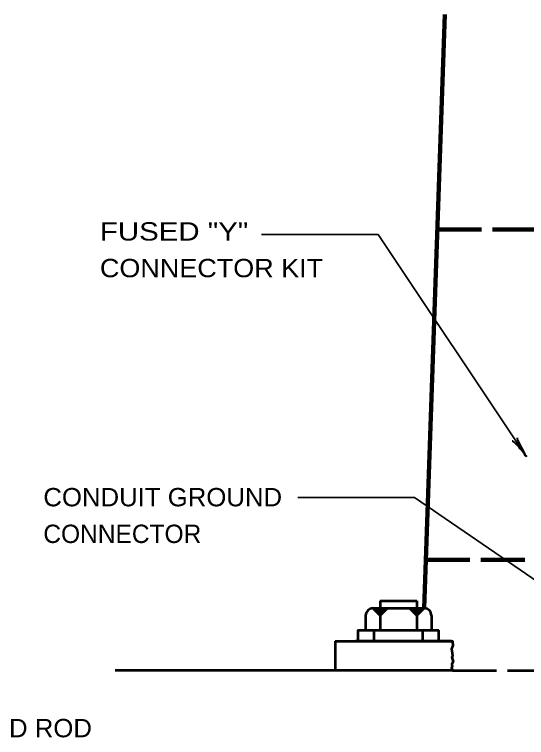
# Model space of a CAD drawing. Extents: x -217 to 639, y -295 to 249.
# Drawn here: x 38.9 to 122.7, y -196.8 to -78.5 of the extents above; entities that cross this region are included whole.
import ezdxf

# ---------------------------------------------------------------- set-up
doc = ezdxf.new("R2010")
doc.units = 0
doc.header["$LTSCALE"] = 1.2
doc.linetypes.add('LONG_DASHED', pattern=[7.5, 6, -1.5])
doc.layers.add('1', color=7, linetype='Continuous', lineweight=53)

msp = doc.modelspace()

# ---------------------------------------------------------------- linework, layer by layer
at = {"layer": '1', "lineweight": 90}
msp.add_line((106, -175.604), (109.392, -78.463), dxfattribs=at)
at = {"layer": '1', "lineweight": 35}
for p, q in [((98.44, -114.451), (79.348, -114.451)), ((98.44, -114.451), (122.733, -150.845)), ((104.401, -157.5), (85.31, -157.5)), ((104.401, -157.5), (141.068, -182.591))]:
    msp.add_line(p, q, dxfattribs=at)
at = {"layer": '1', "linetype": 'LONG_DASHED', "lineweight": 90}
for p, q in [((108.163, -113.668), (159.407, -113.668)), ((106.277, -167.668), (161.293, -167.668))]:
    msp.add_line(p, q, dxfattribs=at)
at = {"layer": '1'}
for p, q in [((98.8, -174.404), (98.8, -179.204)), ((98.8, -174.404), (104.8, -174.404)), ((104.8, -174.404), (104.8, -179.204)), ((97.6, -175.604), (106, -175.604)), ((98.8, -176.804), (97.6, -175.604)), ((97.699, -175.703), (97.798, -175.604)), ((97.715, -175.718), (97.814, -175.619)), ((97.736, -175.739), (97.835, -175.64)), ((97.739, -175.743), (97.839, -175.644)), ((97.745, -175.749), (97.844, -175.65)), ((97.747, -175.75), (97.846, -175.651)), ((97.751, -175.754), (97.85, -175.655)), ((97.758, -175.761), (97.915, -175.604)), ((97.761, -175.765), (97.923, -175.604)), ((97.771, -175.774), (97.941, -175.604)), ((97.775, -175.778), (97.949, -175.604)), ((97.786, -175.79), (97.886, -175.691)), ((97.79, -175.793), (97.979, -175.604)), ((97.797, -175.801), (97.994, -175.604)), ((97.8, -175.803), (97.899, -175.704)), ((97.809, -175.812), (98.017, -175.604)), ((97.813, -175.816), (97.912, -175.717)), ((97.816, -175.82), (97.916, -175.721)), ((97.818, -175.821), (98.036, -175.604)), ((97.831, -175.835), (98.062, -175.604)), ((97.835, -175.839), (97.934, -175.74)), ((97.841, -175.844), (97.94, -175.745)), ((97.844, -175.848), (98.088, -175.604)), ((97.85, -175.853), (98.099, -175.604)), ((97.85, -175.854), (97.949, -175.755)), ((97.854, -175.858), (97.953, -175.759)), ((97.859, -175.863), (98.118, -175.604)), ((97.862, -175.865), (97.961, -175.766)), ((97.865, -175.868), (98.129, -175.604)), ((97.865, -175.868), (98.13, -175.604)), ((97.872, -175.876), (98.145, -175.604)), ((97.878, -175.882), (98.156, -175.604)), ((97.889, -175.893), (98.178, -175.604)), ((97.899, -175.903), (97.998, -175.804)), ((97.903, -175.906), (98.205, -175.604)), ((97.912, -175.916), (98.011, -175.817)), ((97.914, -175.917), (98.227, -175.604)), ((97.918, -175.921), (98.235, -175.604)), ((97.92, -175.924), (98.019, -175.825)), ((97.924, -175.927), (98.023, -175.828)), ((97.927, -175.931), (98.026, -175.832)), ((97.933, -175.937), (98.032, -175.838)), ((97.934, -175.938), (98.269, -175.604)), ((97.944, -175.948), (98.043, -175.849)), ((97.948, -175.951), (98.295, -175.604)), ((97.959, -175.962), (98.318, -175.604)), ((97.959, -175.963), (98.058, -175.864)), ((97.968, -175.972), (98.336, -175.604)), ((97.97, -175.974), (98.34, -175.604)), ((97.983, -175.987), (98.367, -175.604)), ((97.986, -175.989), (98.085, -175.89)), ((97.993, -175.996), (98.385, -175.604)), ((98.002, -176.006), (98.404, -175.604)), ((98.01, -176.013), (98.419, -175.604)), ((98.015, -176.019), (98.431, -175.604)), ((98.021, -176.025), (98.12, -175.926)), ((98.029, -176.032), (98.457, -175.604)), ((98.033, -176.036), (98.132, -175.937)), ((98.034, -176.038), (98.468, -175.604)), ((98.04, -176.043), (98.479, -175.604)), ((98.057, -176.06), (98.513, -175.604)), ((98.06, -176.064), (98.52, -175.604)), ((98.061, -176.065), (98.16, -175.966)), ((98.064, -176.068), (98.528, -175.604)), ((98.072, -176.076), (98.171, -175.977)), ((98.074, -176.077), (98.547, -175.604)), ((98.087, -176.09), (98.573, -175.604)), ((98.087, -176.091), (98.186, -175.992)), ((98.093, -176.096), (98.585, -175.604)), ((98.097, -176.1), (98.196, -176.001)), ((98.1, -176.103), (98.6, -175.604)), ((98.106, -176.109), (98.611, -175.604)), ((98.113, -176.117), (98.626, -175.604)), ((98.117, -176.12), (98.633, -175.604)), ((98.123, -176.127), (98.222, -176.028)), ((98.124, -176.128), (98.649, -175.604)), ((98.129, -176.132), (98.228, -176.033)), ((98.139, -176.143), (98.679, -175.604)), ((98.147, -176.151), (98.246, -176.052)), ((98.147, -176.151), (98.246, -176.052)), ((98.151, -176.154), (98.701, -175.604)), ((98.154, -176.158), (98.709, -175.604)), ((98.168, -176.172), (98.267, -176.073)), ((98.172, -176.175), (98.743, -175.604)), ((98.172, -176.175), (98.743, -175.604)), ((98.175, -176.179), (98.75, -175.604)), ((98.179, -176.182), (98.758, -175.604)), ((98.183, -176.186), (98.765, -175.604)), ((98.187, -176.191), (98.286, -176.092)), ((98.19, -176.194), (98.78, -175.604)), ((98.196, -176.199), (98.791, -175.604)), ((98.196, -176.199), (98.792, -175.604)), ((98.205, -176.209), (98.81, -175.604)), ((98.207, -176.211), (98.306, -176.112)), ((98.217, -176.22), (98.833, -175.604)), ((98.217, -176.221), (98.316, -176.122)), ((98.222, -176.226), (98.844, -175.604)), ((98.228, -176.231), (98.856, -175.604)), ((98.232, -176.235), (98.863, -175.604)), ((98.232, -176.236), (98.331, -176.137)), ((98.234, -176.237), (98.867, -175.604)), ((98.237, -176.241), (98.874, -175.604)), ((98.251, -176.254), (98.901, -175.604)), ((98.266, -176.269), (98.931, -175.604)), ((98.266, -176.27), (98.365, -176.171)), ((98.269, -176.273), (98.369, -176.174)), ((98.275, -176.278), (98.95, -175.604)), ((98.282, -176.286), (98.965, -175.604)), ((98.294, -176.298), (98.393, -176.199)), ((98.296, -176.299), (98.991, -175.604)), ((98.301, -176.305), (99.002, -175.604)), ((98.301, -176.305), (99.002, -175.604)), ((98.305, -176.308), (99.01, -175.604)), ((98.305, -176.308), (99.01, -175.604)), ((98.309, -176.313), (98.408, -176.214)), ((98.313, -176.316), (99.025, -175.604)), ((98.32, -176.323), (99.04, -175.604)), ((98.326, -176.33), (98.425, -176.231)), ((98.33, -176.333), (99.059, -175.604)), ((98.337, -176.341), (98.436, -176.242)), ((98.345, -176.348), (99.089, -175.604)), ((98.348, -176.353), (98.448, -176.254)), ((98.352, -176.355), (99.104, -175.604)), ((98.36, -176.363), (99.119, -175.604)), ((98.361, -176.365), (99.123, -175.604)), ((98.369, -176.372), (99.138, -175.604)), ((98.38, -176.384), (99.16, -175.604)), ((98.392, -176.395), (99.183, -175.604)), ((98.401, -176.404), (99.202, -175.604)), ((98.406, -176.41), (99.213, -175.604)), ((98.412, -176.416), (99.224, -175.604)), ((98.416, -176.419), (99.232, -175.604)), ((98.429, -176.433), (99.258, -175.604)), ((98.435, -176.438), (99.269, -175.604)), ((98.437, -176.441), (99.206, -175.672)), ((98.439, -176.442), (99.277, -175.604)), ((98.448, -176.451), (99.296, -175.604)), ((98.452, -176.455), (99.303, -175.604)), ((98.452, -176.455), (99.303, -175.604)), ((98.456, -176.459), (99.311, -175.604)), ((98.467, -176.47), (99.333, -175.604)), ((98.484, -176.487), (99.367, -175.604)), ((98.489, -176.493), (99.379, -175.604)), ((98.502, -176.506), (99.405, -175.604)), ((98.51, -176.513), (99.42, -175.604)), ((98.521, -176.525), (99.442, -175.604)), ((98.527, -176.53), (99.453, -175.604)), ((98.533, -176.536), (99.465, -175.604)), ((98.538, -176.542), (99.476, -175.604)), ((98.546, -176.549), (99.491, -175.604)), ((98.555, -176.559), (99.51, -175.604)), ((98.568, -176.572), (99.536, -175.604)), ((98.572, -176.575), (99.544, -175.604)), ((98.587, -176.591), (99.574, -175.604)), ((98.598, -176.602), (99.597, -175.604)), ((98.604, -176.608), (99.608, -175.604)), ((98.608, -176.611), (99.616, -175.604)), ((98.623, -176.626), (99.645, -175.604)), ((98.634, -176.638), (99.668, -175.604)), ((98.64, -176.643), (99.679, -175.604)), ((98.647, -176.651), (99.694, -175.604)), ((98.651, -176.655), (99.702, -175.604)), ((98.655, -176.658), (99.709, -175.604)), ((98.666, -176.669), (99.732, -175.604)), ((98.668, -176.671), (99.736, -175.604)), ((98.677, -176.681), (99.754, -175.604)), ((98.677, -176.681), (99.755, -175.604)), ((98.691, -176.694), (99.781, -175.604)), ((98.696, -176.7), (99.792, -175.604)), ((98.709, -176.713), (99.819, -175.604)), ((98.711, -176.715), (99.822, -175.604)), ((98.73, -176.734), (99.86, -175.604)), ((98.738, -176.741), (99.875, -175.604)), ((98.753, -176.756), (99.905, -175.604)), ((98.768, -176.771), (99.935, -175.604)), ((98.768, -176.771), (99.935, -175.604)), ((98.782, -176.786), (99.965, -175.604)), ((98.8, -176.804), (100, -175.604)), ((104.8, -176.804), (103.6, -175.604)), ((104.809, -176.808), (103.609, -175.608)), ((103.623, -175.622), (103.641, -175.604)), ((103.64, -175.639), (103.675, -175.604)), ((103.655, -175.654), (103.705, -175.604)), ((103.662, -175.661), (103.72, -175.604)), ((103.674, -175.673), (103.743, -175.604)), ((103.687, -175.686), (103.769, -175.604)), ((103.698, -175.697), (103.792, -175.604)), ((103.704, -175.703), (103.803, -175.604)), ((103.708, -175.707), (103.807, -175.608)), ((103.723, -175.722), (103.841, -175.604)), ((103.732, -175.731), (103.831, -175.632)), ((103.736, -175.735), (103.835, -175.636)), ((103.743, -175.742), (103.882, -175.604)), ((103.747, -175.746), (103.889, -175.604)), ((103.748, -175.747), (103.847, -175.648)), ((103.753, -175.752), (103.852, -175.653)), ((103.766, -175.765), (103.927, -175.604)), ((103.773, -175.772), (103.942, -175.604)), ((103.779, -175.778), (103.878, -175.679)), ((103.783, -175.782), (103.961, -175.604)), ((103.79, -175.789), (103.976, -175.604)), ((103.795, -175.794), (103.894, -175.695)), ((103.798, -175.797), (103.987, -175.608)), ((103.805, -175.804), (104.006, -175.604)), ((103.808, -175.807), (103.907, -175.708)), ((103.819, -175.817), (104.032, -175.604)), ((103.832, -175.831), (104.059, -175.604)), ((103.834, -175.833), (104.062, -175.604)), ((103.837, -175.836), (104.07, -175.604)), ((103.839, -175.838), (104.074, -175.604)), ((103.843, -175.842), (104.081, -175.604)), ((103.849, -175.848), (104.094, -175.604)), ((103.858, -175.857), (104.107, -175.608)), ((103.873, -175.872), (104.138, -175.608)), ((103.898, -175.897), (104.187, -175.608)), ((103.903, -175.902), (104.202, -175.604)), ((103.911, -175.91), (104.213, -175.608)), ((103.916, -175.915), (104.228, -175.604)), ((103.918, -175.917), (104.232, -175.604)), ((103.926, -175.925), (104.247, -175.604)), ((103.93, -175.929), (104.254, -175.604)), ((103.941, -175.94), (104.04, -175.841)), ((103.943, -175.942), (104.281, -175.604)), ((103.943, -175.942), (104.277, -175.608)), ((103.948, -175.947), (104.292, -175.604)), ((103.956, -175.955), (104.307, -175.604)), ((103.96, -175.959), (104.315, -175.604)), ((103.973, -175.972), (104.341, -175.604)), ((103.978, -175.977), (104.352, -175.604)), ((103.98, -175.979), (104.356, -175.604)), ((103.992, -175.991), (104.379, -175.604)), ((103.995, -175.994), (104.386, -175.604)), ((104.001, -176), (104.397, -175.604)), ((104.001, -176), (104.348, -175.653)), ((104.018, -176.017), (104.431, -175.604)), ((104.027, -176.026), (104.45, -175.604)), ((104.029, -176.029), (104.129, -175.93)), ((104.031, -176.03), (104.458, -175.604)), ((104.039, -176.038), (104.473, -175.604)), ((104.042, -176.041), (104.476, -175.608)), ((104.046, -176.045), (104.488, -175.604)), ((104.048, -176.047), (104.488, -175.608)), ((104.048, -176.047), (104.395, -175.7)), ((104.069, -176.068), (104.529, -175.608)), ((104.08, -176.079), (104.556, -175.604)), ((104.088, -176.087), (104.571, -175.604)), ((104.097, -176.096), (104.589, -175.604)), ((104.101, -176.1), (104.593, -175.608)), ((104.105, -176.104), (104.204, -176.005)), ((104.114, -176.113), (104.623, -175.604)), ((104.114, -176.113), (104.619, -175.608)), ((104.127, -176.126), (104.649, -175.604)), ((104.133, -176.132), (104.657, -175.608)), ((104.14, -176.139), (104.676, -175.604)), ((104.148, -176.147), (104.687, -175.608)), ((104.155, -176.154), (104.706, -175.604)), ((104.155, -176.155), (104.255, -176.056)), ((104.165, -176.164), (104.725, -175.604)), ((104.172, -176.171), (104.74, -175.604)), ((104.176, -176.175), (104.747, -175.604)), ((104.176, -176.176), (104.275, -176.077)), ((104.18, -176.179), (104.755, -175.604)), ((104.183, -176.182), (104.758, -175.608)), ((104.189, -176.188), (104.764, -175.613)), ((104.191, -176.19), (104.777, -175.604)), ((104.204, -176.203), (104.8, -175.608)), ((104.204, -176.203), (104.8, -175.608)), ((104.208, -176.207), (104.811, -175.604)), ((104.214, -176.213), (104.823, -175.604)), ((104.219, -176.218), (104.834, -175.604)), ((104.234, -176.233), (104.864, -175.604)), ((104.236, -176.235), (104.868, -175.604)), ((104.24, -176.24), (104.339, -176.141)), ((104.247, -176.246), (104.89, -175.604)), ((104.259, -176.258), (104.909, -175.608)), ((104.266, -176.265), (104.928, -175.604)), ((104.278, -176.277), (104.951, -175.604)), ((104.283, -176.282), (104.962, -175.604)), ((104.291, -176.29), (104.973, -175.608)), ((104.293, -176.292), (104.981, -175.604)), ((104.3, -176.299), (104.996, -175.604)), ((104.309, -176.308), (105.01, -175.608)), ((104.31, -176.309), (105.014, -175.604)), ((104.311, -176.31), (105.018, -175.604)), ((104.317, -176.317), (104.416, -176.218)), ((104.321, -176.32), (105.037, -175.604)), ((104.327, -176.326), (105.048, -175.604)), ((104.328, -176.327), (105.048, -175.608)), ((104.334, -176.333), (105.063, -175.604)), ((104.334, -176.333), (105.063, -175.604)), ((104.338, -176.337), (105.067, -175.608)), ((104.34, -176.339), (105.075, -175.604)), ((104.342, -176.341), (105.079, -175.604)), ((104.351, -176.35), (105.097, -175.604)), ((104.37, -176.369), (105.131, -175.608)), ((104.377, -176.376), (105.146, -175.608)), ((104.379, -176.378), (105.154, -175.604)), ((104.387, -176.386), (105.167, -175.606)), ((104.388, -176.387), (105.168, -175.608)), ((104.402, -176.401), (105.182, -175.621)), ((104.413, -176.412), (105.193, -175.632)), ((104.415, -176.414), (105.221, -175.608)), ((104.439, -176.438), (105.219, -175.659)), ((104.447, -176.446), (105.285, -175.608)), ((104.455, -176.454), (105.304, -175.604)), ((104.46, -176.459), (105.311, -175.608)), ((104.46, -176.459), (105.24, -175.679)), ((104.47, -176.469), (105.334, -175.604)), ((104.475, -176.474), (105.342, -175.608)), ((104.481, -176.48), (105.261, -175.7)), ((104.483, -176.482), (105.361, -175.604)), ((104.488, -176.487), (105.372, -175.604)), ((104.49, -176.489), (105.27, -175.709)), ((104.501, -176.5), (105.398, -175.604)), ((104.517, -176.516), (105.428, -175.604)), ((104.518, -176.517), (105.428, -175.608)), ((104.522, -176.521), (105.302, -175.741)), ((104.528, -176.527), (105.454, -175.6)), ((104.529, -176.529), (105.451, -175.608)), ((104.533, -176.532), (105.462, -175.604)), ((104.535, -176.534), (105.462, -175.608)), ((104.539, -176.538), (105.473, -175.604)), ((104.552, -176.551), (105.5, -175.604)), ((104.563, -176.562), (105.518, -175.608)), ((104.575, -176.574), (105.545, -175.604)), ((104.577, -176.576), (105.545, -175.608)), ((104.58, -176.579), (105.552, -175.608)), ((104.582, -176.581), (105.56, -175.604)), ((104.595, -176.594), (105.582, -175.608)), ((104.597, -176.596), (105.59, -175.604)), ((104.607, -176.606), (105.605, -175.608)), ((104.612, -176.611), (105.616, -175.608)), ((104.616, -176.615), (105.624, -175.608)), ((104.618, -176.617), (105.631, -175.604)), ((104.631, -176.63), (105.654, -175.608)), ((104.642, -176.641), (105.676, -175.608)), ((104.646, -176.645), (105.688, -175.604)), ((104.655, -176.654), (105.702, -175.608)), ((104.658, -176.657), (105.705, -175.61)), ((104.661, -176.66), (105.708, -175.614)), ((104.673, -176.672), (105.72, -175.625)), ((104.674, -176.673), (105.74, -175.608)), ((104.676, -176.675), (105.744, -175.608)), ((104.685, -176.684), (105.762, -175.608)), ((104.697, -176.696), (105.744, -175.649)), ((104.699, -176.698), (105.789, -175.608)), ((104.703, -176.702), (105.75, -175.655)), ((104.704, -176.703), (105.8, -175.608)), ((104.708, -176.707), (105.755, -175.661)), ((104.718, -176.717), (105.827, -175.608)), ((104.718, -176.717), (105.765, -175.67)), ((104.718, -176.717), (105.765, -175.67)), ((104.72, -176.719), (105.831, -175.608)), ((104.72, -176.719), (105.767, -175.672)), ((104.722, -176.721), (105.839, -175.604)), ((104.725, -176.724), (105.772, -175.678)), ((104.735, -176.734), (105.865, -175.604)), ((104.738, -176.737), (105.868, -175.608)), ((104.744, -176.743), (105.791, -175.696)), ((104.746, -176.745), (105.883, -175.608)), ((104.761, -176.76), (105.913, -175.608)), ((104.776, -176.775), (105.947, -175.604)), ((104.776, -176.775), (105.943, -175.608)), ((104.791, -176.79), (105.973, -175.608)), ((104.8, -176.804), (106, -175.604)), ((104.809, -176.808), (106.009, -175.608)), ((96.4, -176.804), (96.4, -179.204)), ((98.38, -176.385), (98.48, -176.286)), ((98.412, -176.416), (98.511, -176.317)), ((98.422, -176.426), (98.521, -176.327)), ((98.452, -176.456), (98.551, -176.357)), ((98.484, -176.488), (98.583, -176.389)), ((98.604, -176.608), (98.703, -176.509)), ((98.647, -176.652), (98.746, -176.553)), ((98.751, -176.755), (98.85, -176.656)), ((104.389, -176.388), (104.488, -176.289)), ((104.46, -176.46), (104.559, -176.361)), ((104.492, -176.492), (104.591, -176.393)), ((104.528, -176.528), (104.627, -176.429)), ((104.573, -176.573), (104.672, -176.474)), ((104.612, -176.612), (104.711, -176.513)), ((104.656, -176.655), (104.755, -176.556)), ((104.672, -176.672), (104.772, -176.573)), ((104.75, -176.75), (104.849, -176.651)), ((107.2, -176.804), (107.2, -179.204)), ((97.829, -181.004), (97.829, -179.204)), ((105.763, -181.004), (105.763, -179.204)), ((108.4, -181.004), (108.4, -179.204)), ((91.431, -181.004), (91.431, -185.804)), ((91.431, -181.004), (94.765, -181.004)), ((110.439, -181.004), (94.765, -181.004)), ((110.631, -185.804), (55.431, -185.804))]:
    msp.add_line(p, q, dxfattribs=at)
at = {"layer": '1', "linetype": 'LONG_DASHED'}
msp.add_line((110.631, -185.804), (155.631, -185.804), dxfattribs=at)
at = {"layer": '1'}
for points in [[(95.2, -181.004), (95.2, -179.204), (108.4, -179.204)], [(94.765, -181.004), (110.631, -181.004), (110.642, -181.126)], [(110.642, -181.126), (110.697, -181.707), (110.456, -182.249), (110.577, -182.911), (110.637, -183.453), (110.517, -183.633), (110.637, -183.994), (110.757, -184.295), (110.517, -184.777), (110.577, -185.078), (110.456, -185.379), (110.631, -185.804)]]:
    msp.add_lwpolyline(points, dxfattribs=at)
for centre, start, end in [((97.6, -176.804), 90, 180), ((106, -176.804), 0, 90)]:
    msp.add_arc(centre, 1.2, start, end, dxfattribs=at)
at = {"layer": '1', "lineweight": 40}
for centre, major_axis, ratio, start_param, end_param in [((122.197, -149.586), (-0.995, 1.87), 0.07063, 6.2823074, 8.5597026), ((121.73, -149.94), (1.346, -1.678), 0.122415, 0.8963533, 3.1415927)]:
    msp.add_ellipse(centre, major_axis=major_axis, ratio=ratio, start_param=start_param, end_param=end_param, dxfattribs=at)

# ---------------------------------------------------------------- texts
at = {"layer": '1'}
for s, width, p in [('FUSED "Y"', 1.2, (52.919, -115.455)), ('CONNECTOR KIT', 1.1, (52.919, -121.455)), ('CONDUIT GROUND', 1.05, (43.66, -158.934)), ('GROUND ROD', 1.05, (22.363, -196.72))]:
    msp.add_text(s, height=3, dxfattribs=dict(at, width=width)).set_placement(p)
msp.add_text('CONNECTOR', height=3, dxfattribs=at).set_placement((43.66, -164.934))

doc.saveas('drawing.dxf')
